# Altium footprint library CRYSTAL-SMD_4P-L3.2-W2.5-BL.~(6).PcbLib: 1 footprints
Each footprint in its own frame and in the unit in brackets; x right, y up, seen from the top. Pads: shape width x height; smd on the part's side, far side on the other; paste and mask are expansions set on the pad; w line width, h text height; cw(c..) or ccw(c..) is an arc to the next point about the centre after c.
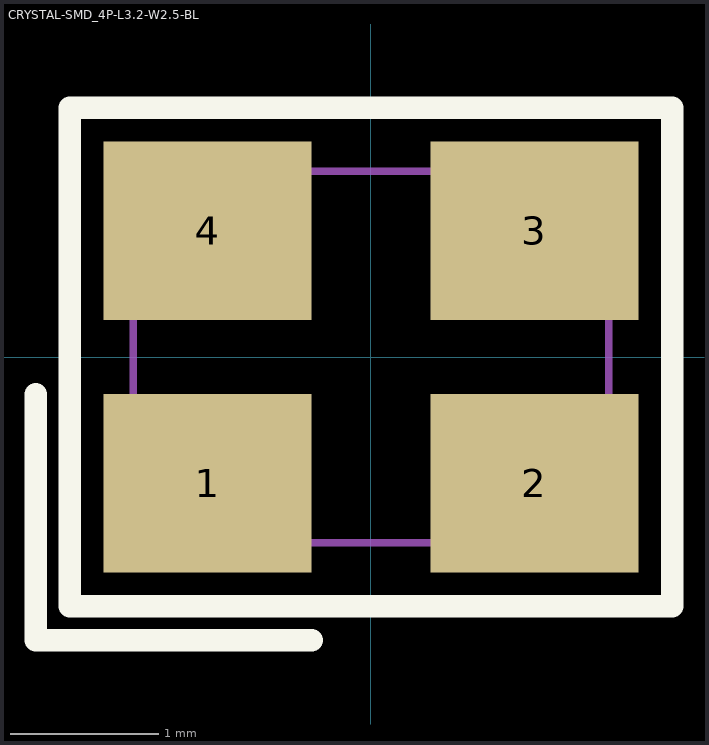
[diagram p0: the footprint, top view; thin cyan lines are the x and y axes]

## CRYSTAL-SMD_4P-L3.2-W2.5-BL [mm]
pads (4):
  rect 1.4x1.2 smd: 1(-1.1,-0.85) 2(1.1,-0.85) 3(1.1,0.85) 4(-1.1,0.85)
Top Overlay:
  lines w0.152: -2.257,-0.25 -2.257,-1.907 -0.4,-1.907 ; -2.029,-1.678 2.029,-1.678 2.029,1.679 -2.029,1.679 -2.029,-1.678
Mechanical 2:
  circle w0.254: c-1.27,-0.889 r0.127
Mechanical 6:
  lines w0.051: -1.6,-1.25 1.6,-1.25 1.6,1.25 -1.6,1.25 -1.6,-1.25
Mechanical 8:
  region: -1.54,-1.25 -1.54,-1.275 -1.575,-1.31 -1.625,-1.31 -1.66,-1.275 -1.66,-1.25 -1.66,-1.225 -1.625,-1.19 -1.575,-1.19 -1.54,-1.225 -1.54,-1.25
Mechanical 9:
  region: -1.5,-0.35 -0.6,-0.35 -0.6,-1.15 -1.5,-1.15
  region: 0.6,-0.35 1.5,-0.35 1.5,-1.15 0.6,-1.15
  region: 0.6,1.15 1.5,1.15 1.5,0.35 0.6,0.35
  region: -1.5,1.15 -0.6,1.15 -0.6,0.35 -1.5,0.35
